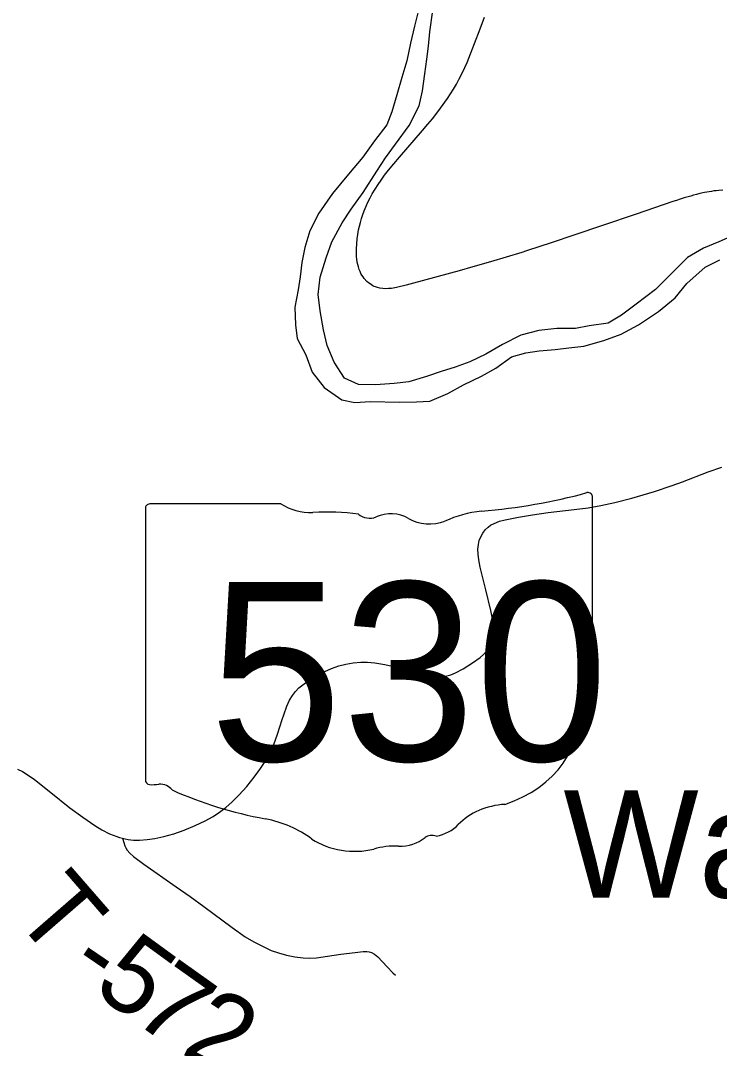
# Model space of a CAD drawing. Extents: x -10 to 158, y 8 to 33.
# Drawn here: x 126.34 to 126.856, y 25.356 to 26.114 of the extents above; entities that cross this region are included whole.
import ezdxf

# ---------------------------------------------------------------- set-up
doc = ezdxf.new("R2010")
doc.units = 0
for name, color, linetype in [('GM_X_Major_River', 7, 'Continuous'), ('GM_X_State_Route', 7, 'Continuous'), ('GM_X_State_Shield', 7, 'Continuous'), ('GM_X_Township_Road', 7, 'Continuous'), ('GM_X_Township_Road_Text', 7, 'Continuous'), ('GM_X_Unincorporated_Text', 7, 'Continuous')]:
    doc.layers.add(name, color=color, linetype=linetype)

msp = doc.modelspace()

# ---------------------------------------------------------------- linework, layer by layer
at = {"layer": 'GM_X_Major_River'}
for points in [[(126.63412, 26.12278), (126.63088, 26.10984), (126.62802, 26.09728), (126.62516, 26.08435), (126.62153, 26.07216), (126.61792, 26.05921), (126.61429, 26.04664), (126.61063, 26.03711), (126.60132, 26.02522), (126.59276, 26.01334), (126.58231, 26.00068), (126.57037, 25.98648), (126.56033, 25.97193), (126.55368, 25.95894), (126.55006, 25.94675), (126.54793, 25.93572), (126.54656, 25.92508), (126.54517, 25.91557), (126.54269, 25.90264), (126.54324, 25.88975), (126.54452, 25.87952), (126.55075, 25.86747), (126.55547, 25.85463), (126.56434, 25.84337), (126.57736, 25.83444), (126.58686, 25.83229), (126.5986, 25.83321), (126.61984, 25.83274), (126.63235, 25.83291), (126.6422, 25.83342), (126.65539, 25.83891), (126.66706, 25.84552), (126.68024, 25.85177), (126.69078, 25.8576), (126.70242, 25.8661), (126.71299, 25.8689), (126.72283, 25.87055), (126.73457, 25.87147), (126.74479, 25.87275), (126.75577, 25.87403), (126.7705, 25.87803), (126.78333, 25.88275), (126.79612, 25.88976), (126.81077, 25.89944), (126.82315, 25.90947), (126.83173, 25.92021), (126.84521, 25.93215), (126.85613, 25.93761)], [(126.86763, 25.95636), (126.8552, 25.95088), (126.84389, 25.94617), (126.83223, 25.93919), (126.81951, 25.92649), (126.80866, 25.91573), (126.7944, 25.90491), (126.78351, 25.89679), (126.77373, 25.89097), (126.75973, 25.88889), (126.74953, 25.88685), (126.73587, 25.88704), (126.72263, 25.88535), (126.7094, 25.88213), (126.69585, 25.87512), (126.68343, 25.86812), (126.67176, 25.86228), (126.66082, 25.85833), (126.65062, 25.85516), (126.63968, 25.8516), (126.62684, 25.84763), (126.61586, 25.84635), (126.60223, 25.8454), (126.58972, 25.84561), (126.57941, 25.8504), (126.57167, 25.86206), (126.56658, 25.87451), (126.56377, 25.88585), (126.5613, 25.89986), (126.56001, 25.91198), (126.56135, 25.9249), (126.56571, 25.93899), (126.57009, 25.95082), (126.57749, 25.96495), (126.58418, 25.97491), (126.59311, 25.98717), (126.60313, 26.00286), (126.60944, 26.01281), (126.61689, 26.02277), (126.62694, 26.03657), (126.63433, 26.05108), (126.63683, 26.06212), (126.63856, 26.07466), (126.63993, 26.08568), (126.64132, 26.09519), (126.64231, 26.10582), (126.64437, 26.12141)]]:
    msp.add_lwpolyline(points, dxfattribs=at)
at = {"layer": 'GM_X_State_Route'}
for points in [[(126.68688, 25.93617), (126.67387, 25.93241), (126.66376, 25.92959), (126.63025, 25.92038), (126.62487, 25.91898), (126.61772, 25.9172), (126.61636, 25.91691), (126.61513, 25.91671), (126.61385, 25.91654), (126.61167, 25.91634), (126.60956, 25.91625), (126.60749, 25.91638), (126.60526, 25.91667), (126.6037, 25.91708), (126.60225, 25.91755), (126.60123, 25.91794), (126.60013, 25.91851), (126.59918, 25.91905), (126.59817, 25.91978), (126.59707, 25.92057), (126.59587, 25.92167), (126.59386, 25.92386), (126.59304, 25.92501), (126.59216, 25.92631), (126.59147, 25.92756), (126.5908, 25.92896), (126.59016, 25.93052), (126.58958, 25.93236), (126.58876, 25.9359), (126.58843, 25.93799), (126.58823, 25.94005), (126.58811, 25.94268), (126.58819, 25.94562), (126.58839, 25.94942), (126.58875, 25.95298), (126.58913, 25.95628), (126.58971, 25.95965), (126.59032, 25.96241), (126.59101, 25.96506), (126.59188, 25.968), (126.59278, 25.97094), (126.59382, 25.97375), (126.59524, 25.97723), (126.59657, 25.98017), (126.59817, 25.98333), (126.59978, 25.98637), (126.60185, 25.98973), (126.60405, 25.99308), (126.60631, 25.99639), (126.6089, 26.00006), (126.61188, 26.0038), (126.61557, 26.00845), (126.61975, 26.01336), (126.63689, 26.03302), (126.64078, 26.03755), (126.6441, 26.0416), (126.64743, 26.04571), (126.65021, 26.04949), (126.65526, 26.05663), (126.65748, 26.06), (126.65961, 26.06349), (126.6618, 26.06724), (126.66391, 26.07111), (126.66612, 26.07531), (126.66811, 26.07948), (126.66968, 26.08299), (126.67105, 26.08637), (126.67926, 26.10788), (126.6826, 26.11649)], [(126.85823, 25.98901), (126.85539, 25.98878), (126.85342, 25.98857), (126.85162, 25.98835), (126.84986, 25.98807), (126.84812, 25.9878), (126.84642, 25.98747), (126.84464, 25.98712), (126.84123, 25.98638), (126.83893, 25.98583), (126.83674, 25.98523), (126.83461, 25.98463), (126.83261, 25.98409), (126.82985, 25.98326), (126.82684, 25.98233), (126.824, 25.98146), (126.82132, 25.98052), (126.79425, 25.97133), (126.76953, 25.96299), (126.74836, 25.95577), (126.73249, 25.95038), (126.7136, 25.94424), (126.71005, 25.94311), (126.68688, 25.93617)], [(126.33815, 25.56201), (126.34199, 25.56017), (126.34618, 25.55767), (126.35065, 25.55443), (126.3627, 25.54469), (126.37685, 25.53349), (126.38638, 25.52648), (126.39514, 25.52051), (126.4005, 25.51725), (126.40611, 25.51439), (126.40872, 25.51323), (126.41136, 25.51225), (126.41348, 25.51153), (126.41561, 25.51099), (126.41768, 25.5105), (126.41981, 25.5101), (126.42169, 25.50986), (126.42374, 25.50971), (126.42816, 25.50964), (126.43382, 25.51005), (126.43941, 25.51085), (126.44615, 25.5123), (126.45338, 25.51437), (126.46105, 25.51705), (126.46915, 25.52036), (126.4765, 25.52384), (126.48253, 25.5272), (126.48726, 25.5303), (126.49176, 25.53372), (126.49648, 25.53785), (126.50138, 25.54269), (126.50725, 25.54919), (126.51274, 25.556), (126.5175, 25.56258), (126.52123, 25.56838), (126.52458, 25.57441), (126.52719, 25.58012), (126.53004, 25.58774), (126.53348, 25.59852), (126.53459, 25.60197), (126.53683, 25.60835), (126.53885, 25.61279), (126.54104, 25.61641), (126.54326, 25.61927), (126.54576, 25.62189), (126.54852, 25.62426), (126.55251, 25.62709), (126.55884, 25.6309), (126.5648, 25.63407), (126.56984, 25.6363), (126.57505, 25.63811), (126.58038, 25.6395), (126.58581, 25.64042), (126.5913, 25.64088), (126.59618, 25.64088), (126.60167, 25.6404), (126.60897, 25.63927), (126.61679, 25.63753), (126.63591, 25.63219), (126.64264, 25.63064), (126.64769, 25.63011), (126.6515, 25.63027), (126.65465, 25.63077), (126.65772, 25.63159), (126.66127, 25.63299), (126.66681, 25.63599), (126.67367, 25.64035), (126.67931, 25.64437), (126.6817, 25.64648), (126.68432, 25.64927), (126.68599, 25.652), (126.68706, 25.6536), (126.68812, 25.6566), (126.68882, 25.65847), (126.68893, 25.6591), (126.68938, 25.66291), (126.68935, 25.66607), (126.68874, 25.67172), (126.68731, 25.67909), (126.68364, 25.69416), (126.6794, 25.71098), (126.67828, 25.71639), (126.67776, 25.72061), (126.67766, 25.72421), (126.67802, 25.72778), (126.6787, 25.73067), (126.67979, 25.73343), (126.68122, 25.73603), (126.68304, 25.73836), (126.6852, 25.7404), (126.68708, 25.74183), (126.68971, 25.74321), (126.69365, 25.74478), (126.69775, 25.7459), (126.70749, 25.74773), (126.71784, 25.74966), (126.72947, 25.75127), (126.74856, 25.75341), (126.75905, 25.75477), (126.76827, 25.75633), (126.77861, 25.75858), (126.79124, 25.76188), (126.8079, 25.76682), (126.82086, 25.77118), (126.82843, 25.77397), (126.84751, 25.78129), (126.85745, 25.78463)]]:
    msp.add_lwpolyline(points, dxfattribs=at)
at = {"layer": 'GM_X_State_Shield'}
for p, q in [((126.53238, 25.75759), (126.43586, 25.75759)), ((126.7622, 25.65787), (126.7622, 25.76255)), ((126.43261, 25.75415), (126.43261, 25.55403)), ((126.76216, 25.65789), (126.7622, 25.65787))]:
    msp.add_line(p, q, dxfattribs=at)
for centre, major_axis, start_param, end_param in [((126.64479, 26.03043), (0.34952, 0), 4.814394, 5.042369), ((126.75854, 25.76299), (0.00367, 0), 6.141152, 7.989035), ((126.43639, 25.75458), (0.00382, 0), 1.712693, 3.28349), ((126.55536, 25.78083), (0.03703, 0), 4.042523, 4.731795), ((126.56764, 25.64524), (0.13295, 0), 1.404758, 1.657858), ((126.59783, 25.75561), (0.01068, 0), 3.836095, 5.185415), ((126.61351, 25.73248), (0.02221, 0), 0.950623, 2.079405), ((126.68938, 25.69647), (0.07032, 0), 1.699011, 2.107814), ((126.64218, 25.76421), (0.02672, 0), 4.081561, 5.145723), ((126.76135, 25.65018), (0.00568, 0), 1.883978, 3.671073), ((126.75828, 25.65746), (0.00393, 0), 5.05454, 6.418171), ((126.72522, 25.63695), (0.03409, 0), 5.934695, 6.695948), ((126.77534, 25.61406), (0.0248, 0), 2.387724, 3.262537), ((126.66437, 25.60074), (0.08742, 0), 5.101752, 6.440018), ((126.43642, 25.55359), (0.00385, 0), 3.00124, 4.508301), ((126.43701, 25.57407), (0.0294, 0), 4.665946, 4.897461), ((126.44302, 25.54248), (0.0106, 0), 0.519207, 1.627899), ((126.57685, 25.72228), (0.2524, 0), 4.195997, 4.488961), ((126.70123, 25.49785), (0.04788, 0), 1.647645, 2.488434), ((126.5016, 25.46413), (0.07897, 0), 0.823519, 1.323587), ((126.64057, 25.53463), (0.02824, 0), 4.937069, 5.64225), ((126.58701, 25.54149), (0.05011, 0), 4.026481, 4.996735), ((126.61962, 25.52651), (0.0267, 0), 4.691044, 5.507374), ((126.64378, 25.50712), (0.00752, 0), 1.147584, 2.315152), ((126.61596, 25.4723), (0.04118, 0), 1.495662, 1.94098)]:
    msp.add_ellipse(centre, major_axis=major_axis, ratio=0.8, start_param=start_param, end_param=end_param, dxfattribs=at)
at = {"layer": 'GM_X_Township_Road'}
msp.add_lwpolyline([(126.41561, 25.51099), (126.41654, 25.50794), (126.41739, 25.50541), (126.4181, 25.50392), (126.41908, 25.50237), (126.42109, 25.50001), (126.42386, 25.49752), (126.43137, 25.49201), (126.45532, 25.47529), (126.46549, 25.46813), (126.47553, 25.4608), (126.49648, 25.44525), (126.50613, 25.43845), (126.51255, 25.43464), (126.52027, 25.43063), (126.52537, 25.42833), (126.53063, 25.42644), (126.53663, 25.42481), (126.54272, 25.42362), (126.54888, 25.42283), (126.55383, 25.42265), (126.55878, 25.42296), (126.56678, 25.42404), (126.57661, 25.42549), (126.5871, 25.42677), (126.59308, 25.42749), (126.59574, 25.42764), (126.59757, 25.42734), (126.59933, 25.42673), (126.60147, 25.42548), (126.60387, 25.4235), (126.61078, 25.41633), (126.61504, 25.41182), (126.61682, 25.4101)], dxfattribs=at)

# ---------------------------------------------------------------- texts
at = {"layer": 'GM_X_State_Shield'}
msp.add_text('530', height=0.131836, dxfattribs=at).set_placement((126.47956, 25.56814))
at = {"layer": 'GM_X_Township_Road_Text'}
for s, rotation, p in [('T', 310.98758, (126.33382, 25.45426)), ('5', 323.92633, (126.39245, 25.39876)), ('-', 325.70541, (126.37356, 25.41164)), ('7', 324.58791, (126.42132, 25.37773)), ('2', 332.95622, (126.45758, 25.35277))]:
    msp.add_text(s, height=0.05682, rotation=rotation, dxfattribs=at).set_placement(p)
at = {"layer": 'GM_X_Unincorporated_Text'}
msp.add_text('Warner', height=0.078977, rotation=0.00001, dxfattribs=at).set_placement((126.74076, 25.46729))

doc.saveas('drawing.dxf')
